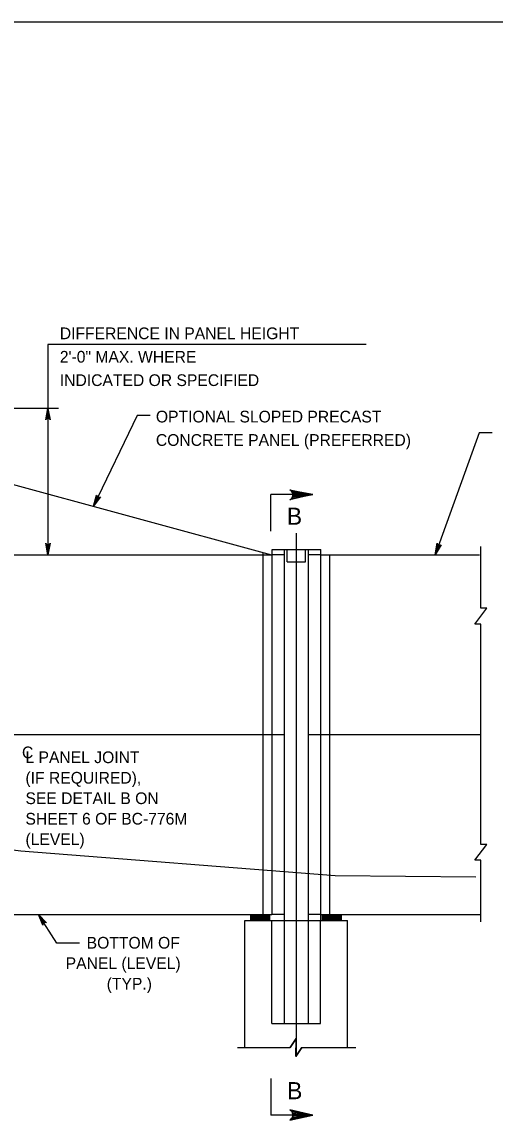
# Model space of a CAD drawing. Extents: x 3761 to 5458, y -616 to 1166.
# Drawn here: x 4160.9 to 4284.9, y 268.6 to 556.7 of the extents above; entities that cross this region are included whole.
import ezdxf

# ---------------------------------------------------------------- set-up
doc = ezdxf.new("R2010")
doc.units = 0
doc.layers.add('1', color=7, linetype='Continuous')
doc.layers.add('2', color=7, linetype='Continuous')

msp = doc.modelspace()

# ---------------------------------------------------------------- linework, layer by layer
at = {"layer": '1'}
for p, q in [((4167.67, 472.08), (4167.67, 416.9)), ((4251.06, 472.08), (4167.67, 472.08)), ((4085.41, 455.3), (4226.32, 416.9)), ((4170.46, 455.3), (4091.37, 455.3)), ((4191.05, 453.44), (4179.63, 429.63)), ((4194.46, 453.44), (4191.05, 453.44)), ((4280.69, 448.88), (4269.23, 416.9)), ((4284.1, 448.88), (4280.69, 448.88)), ((4226.07, 423.04), (4226.07, 432.69)), ((4237.08, 432.69), (4226.07, 432.69)), ((4232.83, 285.42), (4232.83, 422.52)), ((4226.48, 322.48), (4226.48, 418.26)), ((4226.48, 418.26), (4239.18, 418.26)), ((4229.66, 293.91), (4229.66, 418.26)), ((4230.43, 415.06), (4230.43, 418.26)), ((4235.23, 415.06), (4235.23, 418.26)), ((4236, 293.91), (4236, 418.26)), ((4239.18, 320.89), (4239.18, 418.26)), ((4281.14, 402.85), (4281.14, 419.06)), ((4085.41, 416.9), (4226.32, 416.9)), ((4224.08, 322.48), (4224.08, 417.51)), ((4229.49, 416.9), (4226.32, 416.9)), ((4230.43, 415.06), (4235.23, 415.06)), ((4239.01, 416.9), (4235.84, 416.9)), ((4239.01, 416.9), (4280.81, 416.9)), ((4241.58, 322.48), (4241.58, 416.9)), ((4281.14, 340.9), (4281.14, 398.67)), ((4082.24, 369.69), (4229.66, 369.69)), ((4236, 369.69), (4281.14, 369.69)), ((4281.14, 320.56), (4281.14, 336.73)), ((4085.41, 322.48), (4226.4, 322.48)), ((4169.99, 314.96), (4165.18, 322.48)), ((4219.25, 320.89), (4246.24, 320.89)), ((4219.25, 287.56), (4219.25, 320.89)), ((4220.84, 320.89), (4220.84, 322.48)), ((4220.84, 322.29), (4225.83, 322.29)), ((4220.84, 322.09), (4225.83, 322.09)), ((4220.84, 321.89), (4225.83, 321.89)), ((4220.84, 321.69), (4225.83, 321.69)), ((4220.84, 321.49), (4225.83, 321.49)), ((4220.84, 321.29), (4225.83, 321.29)), ((4220.84, 321.09), (4225.83, 321.09)), ((4220.84, 320.89), (4225.83, 320.89)), ((4225.83, 320.89), (4225.83, 322.48)), ((4229.57, 322.48), (4226.4, 322.48)), ((4226.4, 293.91), (4226.4, 320.89)), ((4239.09, 322.48), (4235.92, 322.48)), ((4239.09, 322.48), (4281.14, 322.48)), ((4239.09, 293.91), (4239.09, 320.89)), ((4239.65, 320.89), (4239.65, 322.48)), ((4239.65, 322.29), (4244.65, 322.29)), ((4239.65, 322.09), (4244.65, 322.09)), ((4239.65, 321.89), (4244.65, 321.89)), ((4239.65, 321.69), (4244.65, 321.69)), ((4239.65, 321.49), (4244.65, 321.49)), ((4239.65, 321.29), (4244.65, 321.29)), ((4239.65, 321.09), (4244.65, 321.09)), ((4244.65, 320.89), (4244.65, 322.48)), ((4246.24, 287.56), (4246.24, 320.89)), ((4175.96, 314.96), (4169.99, 314.96)), ((4226.4, 293.91), (4239.09, 293.91)), ((4231.19, 287.56), (4232.71, 289.91)), ((4232.71, 289.91), (4232.69, 285.21)), ((4217.4, 287.56), (4231.19, 287.56)), ((4232.69, 285.21), (4234.21, 287.56)), ((4234.21, 287.56), (4248.43, 287.56)), ((4226.07, 279.47), (4226.07, 269.82)), ((4237.08, 269.82), (4226.07, 269.82))]:
    msp.add_line(p, q, dxfattribs=at)
for points in [[(4167.67, 455.3), (4168.23, 452.32), (4168.15, 452.44), (4168.07, 452.55), (4167.97, 452.61), (4167.87, 452.67), (4167.77, 452.69), (4167.67, 452.7), (4167.57, 452.69), (4167.47, 452.67), (4167.37, 452.61), (4167.27, 452.55), (4167.19, 452.44), (4167.11, 452.32), (4167.67, 455.3), (4167.19, 452.44), (4167.27, 452.55), (4167.67, 455.3), (4167.37, 452.61), (4167.47, 452.67), (4167.67, 455.3), (4167.57, 452.69), (4167.67, 452.7), (4167.67, 455.3), (4167.77, 452.69), (4167.87, 452.67), (4167.67, 455.3), (4167.97, 452.61), (4168.07, 452.55), (4167.67, 455.3), (4168.15, 452.44)], [(4179.63, 429.63), (4180.41, 432.56), (4180.44, 432.42), (4180.46, 432.28), (4180.52, 432.18), (4180.59, 432.09), (4180.67, 432.03), (4180.75, 431.97), (4180.85, 431.94), (4180.95, 431.92), (4181.06, 431.93), (4181.18, 431.94), (4181.3, 432), (4181.42, 432.07), (4179.63, 429.63), (4181.3, 432), (4181.18, 431.94), (4179.63, 429.63), (4181.06, 431.93), (4180.95, 431.92), (4179.63, 429.63), (4180.85, 431.94), (4180.75, 431.97), (4179.63, 429.63), (4180.67, 432.03), (4180.59, 432.09), (4179.63, 429.63), (4180.52, 432.18), (4180.46, 432.28), (4179.63, 429.63), (4180.44, 432.42)], [(4237.08, 432.69), (4231.12, 431.27), (4231.35, 431.46), (4231.58, 431.66), (4231.7, 431.9), (4231.81, 432.14), (4231.84, 432.38), (4231.88, 432.62), (4231.84, 432.86), (4231.8, 433.1), (4231.68, 433.34), (4231.56, 433.58), (4231.33, 433.76), (4231.1, 433.95), (4237.08, 432.69), (4231.33, 433.76), (4231.56, 433.58), (4237.08, 432.69), (4231.68, 433.34), (4231.8, 433.1), (4237.08, 432.69), (4231.84, 432.86), (4231.88, 432.62), (4237.08, 432.69), (4231.84, 432.38), (4231.81, 432.14), (4237.08, 432.69), (4231.7, 431.9), (4231.58, 431.66), (4237.08, 432.69), (4231.35, 431.46)], [(4167.67, 416.9), (4167.11, 419.89), (4167.19, 419.77), (4167.27, 419.66), (4167.37, 419.6), (4167.47, 419.54), (4167.57, 419.52), (4167.67, 419.5), (4167.77, 419.52), (4167.87, 419.54), (4167.97, 419.6), (4168.07, 419.66), (4168.15, 419.77), (4168.23, 419.89), (4167.67, 416.9), (4168.15, 419.77), (4168.07, 419.66), (4167.67, 416.9), (4167.97, 419.6), (4167.87, 419.54), (4167.67, 416.9), (4167.77, 419.52), (4167.67, 419.5), (4167.67, 416.9), (4167.57, 419.52), (4167.47, 419.54), (4167.67, 416.9), (4167.37, 419.6), (4167.27, 419.66), (4167.67, 416.9), (4167.19, 419.77)], [(4269.23, 416.9), (4269.71, 419.9), (4269.78, 419.63), (4269.93, 419.45), (4270.1, 419.35), (4270.3, 419.32), (4270.53, 419.36), (4270.76, 419.52), (4269.23, 416.9), (4270.53, 419.36), (4270.3, 419.32), (4269.23, 416.9), (4270.1, 419.35), (4269.93, 419.45), (4269.23, 416.9), (4269.78, 419.63)], [(4281.14, 398.67), (4279.55, 398.67), (4282.73, 402.85), (4281.14, 402.85)], [(3861.98, 350.45), (3878.35, 350.9), (3891.12, 350.32), (3914.31, 351.17), (3937.57, 351.17), (3961.32, 351.07), (3966.64, 351.17), (3982.01, 351.07), (3996.76, 351.17), (4011.56, 350.95), (4046.92, 351.17), (4066.47, 350.64), (4086.26, 348.09), (4094.49, 346.67), (4106.93, 345.35), (4120.71, 343.61), (4143.22, 341.33), (4160.6, 339.19), (4243, 332.75), (4279.86, 332.38)], [(4281.14, 336.73), (4279.55, 336.73), (4282.73, 340.9), (4281.14, 340.9)], [(4165.18, 322.48), (4167.26, 320.27), (4167, 320.37), (4166.77, 320.37), (4166.58, 320.29), (4166.43, 320.15), (4166.33, 319.94), (4166.32, 319.66), (4165.18, 322.48), (4166.33, 319.94), (4166.43, 320.15), (4165.18, 322.48), (4166.58, 320.29), (4166.77, 320.37), (4165.18, 322.48), (4167, 320.37)], [(4217.4, 287.56), (4231.19, 287.56), (4232.71, 289.91), (4232.69, 285.21), (4234.21, 287.56), (4248.43, 287.56)], [(4234.21, 287.56), (4232.69, 285.21), (4232.71, 289.91), (4231.19, 287.56)], [(4237.08, 269.82), (4231.12, 271.24), (4231.35, 271.05), (4231.58, 270.85), (4231.7, 270.61), (4231.81, 270.37), (4231.84, 270.13), (4231.88, 269.89), (4231.84, 269.65), (4231.8, 269.41), (4231.68, 269.17), (4231.56, 268.93), (4231.33, 268.74), (4231.1, 268.56), (4237.08, 269.82), (4231.33, 268.74), (4231.56, 268.93), (4237.08, 269.82), (4231.68, 269.17), (4231.8, 269.41), (4237.08, 269.82), (4231.84, 269.65), (4231.88, 269.89), (4237.08, 269.82), (4231.84, 270.13), (4231.81, 270.37), (4237.08, 269.82), (4231.7, 270.61), (4231.58, 270.85), (4237.08, 269.82), (4231.35, 271.05)]]:
    msp.add_lwpolyline(points, dxfattribs=at)
at = {"layer": '2'}
msp.add_line((3801.34, 556.69), (4587.34, 556.69), dxfattribs=at)

# ---------------------------------------------------------------- texts
at = {"layer": '1'}
for s, height, p in [('DIFFERENCE IN PANEL HEIGHT', 3.072, (4170.78, 473.45)), ('2\'-0" MAX. WHERE ', 3.072, (4170.78, 467.3)), ('INDICATED OR SPECIFIED', 3.072, (4170.78, 461.16)), ('OPTIONAL SLOPED PRECAST', 3.072, (4195.97, 451.6)), ('CONCRETE PANEL (PREFERRED)', 3.072, (4195.97, 445.46)), ('B', 4.48, (4230.3, 424.77)), ('C', 3.07, (4160.86, 363.49)), ('L PANEL JOINT', 3.072, (4161.77, 362.21)), ('(IF REQUIRED), ', 3.072, (4161.77, 356.83)), ('SEE DETAIL B ON', 3.072, (4161.77, 351.46)), ('SHEET 6 OF BC-776M', 3.072, (4161.77, 346.08)), ('(LEVEL)', 3.072, (4161.77, 340.71)), ('BOTTOM OF', 3.072, (4177.82, 313.54)), ('PANEL (LEVEL)', 3.072, (4172.32, 308.17)), ('(TYP.)', 3.072, (4183.07, 302.79)), ('B', 4.48, (4230.37, 274.02))]:
    msp.add_text(s, height=height, dxfattribs=at).set_placement(p)

doc.saveas('drawing.dxf')
